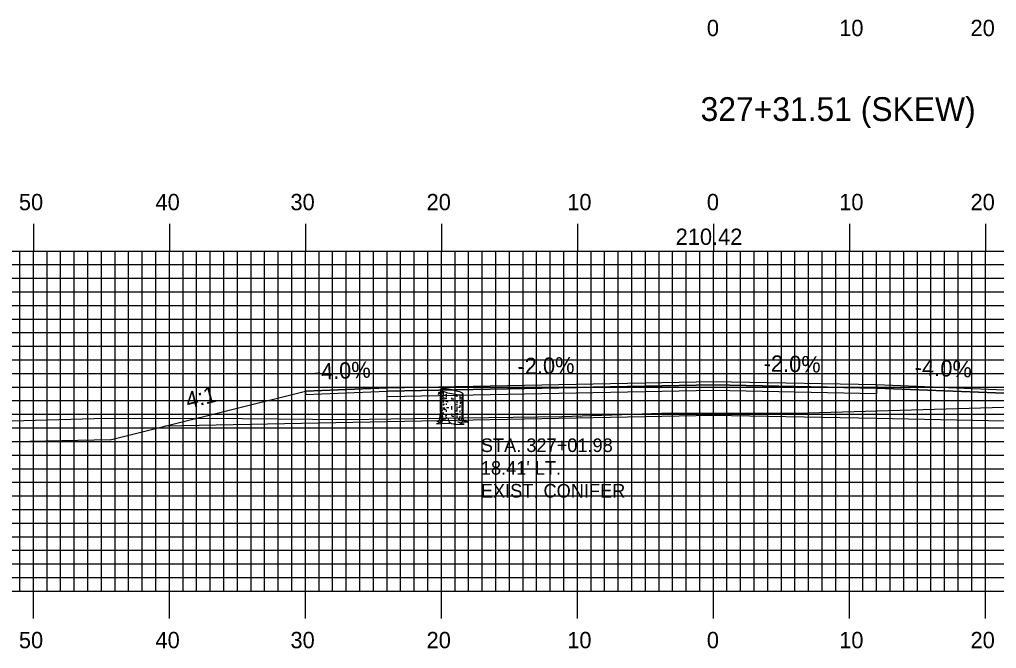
# Model space of a CAD drawing. Extents: x 1821605 to 1821948, y 442591 to 442811.
# Drawn here: x 1821719.7 to 1821791.6, y 442644.4 to 442690.7 of the extents above; entities that cross this region are included whole.
import ezdxf

# ---------------------------------------------------------------- set-up
doc = ezdxf.new("R2010")
doc.units = 0
for name, color, linetype in [('ANNOTATION', 7, 'Continuous'), ('D_Roadway_Centerline', 7, 'Continuous'), ('D_Roadway_Centerline_Text', 7, 'Continuous'), ('D_Roadway_Edge_Shoulder', 7, 'Continuous'), ('D_Roadway_Edge_TW', 7, 'Continuous'), ('D_Roadway_Pavement', 7, 'Continuous'), ('D_Roadway_SubGrade', 7, 'Continuous'), ('D_Text_Monospaced', 7, 'Continuous'), ('H_V ANNOTATION', 7, 'Continuous'), ('M_Trees_Conifer_Pay', 7, 'Continuous'), ('MAJOR', 7, 'Continuous'), ('MINOR', 7, 'Continuous'), ('S_Roadway_Centerline', 7, 'Continuous')]:
    doc.layers.add(name, color=color, linetype=linetype)

msp = doc.modelspace()

# ---------------------------------------------------------------- linework, layer by layer
at = {"layer": 'ANNOTATION'}
msp.add_line((1821726.395, 442659.778), (1821630.743, 442657.865), dxfattribs=at)
at = {"layer": 'D_Roadway_Centerline'}
msp.add_lwpolyline([(1821726.395, 442659.778), (1821730.395, 442660.778), (1821740.743, 442663.365), (1821746.743, 442663.605), (1821770.743, 442664.085), (1821782.743, 442663.845), (1821792.743, 442663.445), (1821802.743, 442660.945), (1821806.743, 442659.945), (1821816.975, 442662.503), (1821818.225, 442662.782), (1821819.475, 442662.992), (1821820.725, 442663.135), (1821821.975, 442663.209)], dxfattribs=at)
at = {"layer": 'D_Roadway_Edge_Shoulder'}
for points in [[(1821746.743, 442663.605), (1821740.743, 442663.365), (1821740.743, 442663.115), (1821746.743, 442663.355)], [(1821782.743, 442663.845), (1821792.743, 442663.445), (1821792.743, 442663.195), (1821782.743, 442663.595)]]:
    msp.add_lwpolyline(points, close=True, dxfattribs=at)
at = {"layer": 'D_Roadway_Edge_TW'}
msp.add_lwpolyline([(1821746.743, 442663.355), (1821746.743, 442663.605), (1821770.743, 442664.085), (1821782.743, 442663.845), (1821782.743, 442663.595), (1821770.743, 442663.835)], close=True, dxfattribs=at)
at = {"layer": 'D_Roadway_Pavement'}
msp.add_lwpolyline([(1821746.743, 442662.939), (1821746.743, 442663.355), (1821770.743, 442663.835), (1821782.743, 442663.595), (1821782.743, 442663.179), (1821770.743, 442663.419)], close=True, dxfattribs=at)
at = {"layer": 'D_Roadway_SubGrade'}
msp.add_lwpolyline([(1821746.743, 442661.105), (1821730.395, 442660.778), (1821740.743, 442663.365), (1821740.743, 442663.115), (1821746.743, 442663.355), (1821770.743, 442663.835), (1821782.743, 442663.595), (1821792.743, 442663.195), (1821792.743, 442663.445), (1821802.743, 442660.945), (1821782.743, 442661.345), (1821770.743, 442661.585)], close=True, dxfattribs=at)
at = {"layer": 'M_Trees_Conifer_Pay'}
for p, q in [((1821750.674, 442661.839), (1821750.674, 442663.486)), ((1821750.745, 442663.414), (1821750.745, 442663.251)), ((1821750.863, 442663.353), (1821750.863, 442663.13)), ((1821750.745, 442663.183), (1821750.745, 442663.056)), ((1821750.745, 442662.869), (1821750.745, 442662.533)), ((1821750.806, 442662.858), (1821750.857, 442662.798)), ((1821750.863, 442663.041), (1821750.863, 442662.994)), ((1821750.863, 442662.659), (1821750.863, 442662.527)), ((1821751.091, 442663.157), (1821751.091, 442662.957)), ((1821751.091, 442662.899), (1821751.091, 442662.811)), ((1821751.482, 442662.883), (1821751.482, 442662.788)), ((1821751.887, 442663.115), (1821751.887, 442662.947)), ((1821751.887, 442662.71), (1821751.887, 442662.473)), ((1821752.107, 442663.094), (1821752.107, 442662.862)), ((1821752.107, 442662.821), (1821752.107, 442662.747)), ((1821752.232, 442663.102), (1821752.232, 442663.004)), ((1821752.232, 442662.93), (1821752.232, 442662.726)), ((1821752.232, 442662.668), (1821752.232, 442662.469)), ((1821752.291, 442663.113), (1821752.291, 442662.642)), ((1821752.291, 442662.578), (1821752.291, 442662.269)), ((1821752.338, 442661.429), (1821752.338, 442663.151)), ((1821750.745, 442662.496), (1821750.745, 442662.333)), ((1821750.745, 442662.286), (1821750.745, 442662.069)), ((1821750.745, 442662.038), (1821750.745, 442661.964)), ((1821750.745, 442661.924), (1821750.745, 442661.75)), ((1821750.863, 442662.416), (1821750.863, 442662.306)), ((1821750.863, 442662.17), (1821750.863, 442662.029)), ((1821751.091, 442662.463), (1821751.091, 442662.358)), ((1821751.091, 442661.991), (1821751.091, 442661.845)), ((1821751.482, 442662.269), (1821751.482, 442662.195)), ((1821751.482, 442662.17), (1821751.482, 442662.022)), ((1821751.887, 442662.228), (1821751.887, 442662.076)), ((1821751.887, 442662.033), (1821751.887, 442661.859)), ((1821752.107, 442662.344), (1821752.107, 442662.205)), ((1821752.107, 442661.933), (1821752.107, 442661.792)), ((1821752.232, 442662.422), (1821752.232, 442662.086)), ((1821752.232, 442662.033), (1821752.232, 442661.897)), ((1821752.291, 442662.222), (1821752.291, 442661.73)), ((1821750.863, 442661.802), (1821750.863, 442661.629)), ((1821751.091, 442661.613), (1821751.091, 442661.524)), ((1821751.482, 442661.73), (1821751.482, 442661.577)), ((1821751.887, 442661.582), (1821751.887, 442661.429)), ((1821752.107, 442661.53), (1821752.107, 442661.435)), ((1821752.232, 442661.798), (1821752.232, 442661.419)), ((1821752.291, 442661.676), (1821752.291, 442661.429)), ((1821751.67, 442660.972), (1821751.796, 442661.036)), ((1821752.107, 442661.036), (1821751.944, 442661.099))]:
    msp.add_line(p, q, dxfattribs=at)
for points in [[(1821750.857, 442662.984), (1821750.82, 442662.91), (1821750.773, 442662.967), (1821750.715, 442663.035), (1821750.623, 442663.229), (1821750.558, 442663.276), (1821750.527, 442663.283)], [(1821750.628, 442663.217), (1821750.552, 442663.225), (1821750.48, 442663.126)], [(1821750.842, 442662.731), (1821750.806, 442662.858), (1821750.742, 442662.973), (1821750.711, 442663.041), (1821750.642, 442663.187)], [(1821750.89, 442662.947), (1821750.921, 442662.862), (1821750.925, 442662.794), (1821750.894, 442662.731)], [(1821751.02, 442662.057), (1821751.007, 442661.981), (1821750.96, 442661.991), (1821750.972, 442662.158)], [(1821752.159, 442662.456), (1821752.165, 442662.552), (1821752.121, 442662.529), (1821752.121, 442662.434)], [(1821750.674, 442661.839), (1821750.623, 442661.577), (1821750.606, 442661.304), (1821750.548, 442661.178), (1821750.413, 442661.147), (1821750.643, 442661.11), (1821750.643, 442661.11), (1821750.637, 442661.063), (1821750.39, 442660.968), (1821750.664, 442660.985), (1821751.02, 442661.005), (1821751.341, 442660.995), (1821751.335, 442661.077), (1821751.483, 442660.995), (1821751.67, 442660.972), (1821751.646, 442660.904), (1821751.913, 442660.947), (1821752.134, 442660.92), (1821752.426, 442660.937), (1821752.138, 442660.995), (1821752.107, 442661.036), (1821752.27, 442661.094), (1821752.506, 442661.104), (1821752.747, 442661.104), (1821752.405, 442661.162), (1821752.364, 442661.242), (1821752.338, 442661.429)], [(1821750.847, 442661.551), (1821750.773, 442661.446), (1821750.768, 442661.273), (1821750.643, 442661.11)], [(1821750.748, 442661.697), (1821750.742, 442661.551), (1821750.695, 442661.483), (1821750.684, 442661.283)], [(1821750.806, 442661.057), (1821750.82, 442661.195), (1821750.894, 442661.324)], [(1821751.084, 442661.446), (1821751.073, 442661.32), (1821750.999, 442661.277)], [(1821751.335, 442661.077), (1821751.26, 442661.219), (1821751.251, 442661.32)], [(1821751.823, 442661.147), (1821751.755, 442661.242), (1821751.728, 442661.382)], [(1821752.049, 442661.388), (1821752.049, 442661.256), (1821752.138, 442661.157)], [(1821752.212, 442661.361), (1821752.206, 442661.246), (1821752.259, 442661.157), (1821752.27, 442661.094)], [(1821752.29, 442661.382), (1821752.311, 442661.304), (1821752.331, 442661.209)]]:
    msp.add_lwpolyline(points, dxfattribs=at)
for centre, radius, start, end in [((1821750.696, 442663.486), 0.0226, 156.59265, 168.2806), ((1821750.696, 442663.486), 0.0226, 168.2806, 179.96855), ((1821750.7, 442663.486), 0.0264, 179.96855, 190.7806), ((1821750.705, 442663.487), 0.0314, 190.7806, 203.48418), ((1821750.707, 442663.36), 0.0334, 185.78494, 196.05154), ((1821750.717, 442663.363), 0.0441, 196.05154, 210), ((1821750.7, 442663.485), 0.0264, 145.7806, 156.59265), ((1821750.725, 442663.496), 0.0527, 203.48418, 213.2806), ((1821750.704, 442663.482), 0.0314, 133.07702, 145.7806), ((1821750.733, 442663.372), 0.0624, 210, 228.74941), ((1821750.749, 442663.511), 0.0817, 213.2806, 227.61132), ((1821750.719, 442663.466), 0.0527, 123.2806, 133.07702), ((1821750.734, 442663.442), 0.0817, 108.94987, 123.2806), ((1821750.806, 442663.454), 0.172, 228.74941, 240), ((1821750.863, 442663.636), 0.251, 227.61132, 235.7806), ((1821750.789, 442663.282), 0.251, 100.7806, 108.94987), ((1821751.173, 442664.092), 0.802, 235.7806, 251.94061), ((1821750.892, 442662.741), 0.802, 84.62059, 100.7806), ((1821752.529, 442668.253), 5.179, 251.94061, 258.2806), ((1821750.482, 442658.383), 5.179, 78.2806, 84.62059), ((1821750.482, 442658.383), 5.179, 71.94061, 78.2806), ((1821751.839, 442662.545), 0.802, 55.7806, 71.94061), ((1821750.707, 442663.205), 0.0334, 185.78494, 196.05154), ((1821750.707, 442662.761), 0.0334, 185.78494, 196.05154), ((1821750.717, 442663.208), 0.0441, 196.05154, 210), ((1821750.733, 442663.217), 0.0624, 210, 228.74941), ((1821750.806, 442663.3), 0.172, 228.74941, 240), ((1821751.005, 442663.645), 0.571, 240, 242.9763), ((1821751.005, 442663.201), 0.571, 242.95715, 255.55072), ((1821751.005, 442663.799), 0.571, 247.58675, 255.56834), ((1821751.005, 442663.645), 0.571, 255.63335, 261.8968), ((1821751.506, 442667.163), 4.124, 261.8968, 263.76196), ((1821751.507, 442666.93), 4.124, 262.94416, 264.21507), ((1821751.506, 442666.719), 4.124, 264.04957, 266.29476), ((1821752.529, 442668.253), 5.179, 258.2806, 264.62059), ((1821751.507, 442666.93), 4.124, 269.64186, 270), ((1821751.507, 442666.93), 4.124, 270, 271.92488), ((1821751.506, 442667.163), 4.124, 273.26691, 275.3045), ((1821752.119, 442663.895), 0.802, 264.62059, 280.7806), ((1821752.008, 442663.412), 0.571, 282.01543, 293.14027), ((1821752.007, 442663.201), 0.571, 292.94134, 300), ((1821752.222, 442663.354), 0.251, 280.7806, 288.94988), ((1821752.149, 442663), 0.251, 47.61132, 55.7806), ((1821752.008, 442663.412), 0.571, 299.66328, 300), ((1821752.207, 442663.067), 0.172, 300, 311.25059), ((1821752.277, 442663.194), 0.0817, 288.94988, 303.2806), ((1821752.263, 442663.125), 0.0817, 33.2806, 47.61132), ((1821752.28, 442662.985), 0.0624, 311.25059, 330), ((1821752.293, 442663.17), 0.0527, 303.2806, 313.07702), ((1821752.307, 442663.155), 0.0314, 313.07702, 325.7806), ((1821752.287, 442663.141), 0.0527, 23.48418, 33.2806), ((1821752.312, 442663.152), 0.0264, 325.7806, 336.59265), ((1821752.295, 442662.975), 0.0441, 330, 343.94846), ((1821752.306, 442663.149), 0.0314, 10.7806, 23.48418), ((1821752.315, 442663.15), 0.0226, 336.59265, 348.2806), ((1821752.311, 442663.15), 0.0264, 359.96855, 10.7806), ((1821752.315, 442663.15), 0.0226, 348.2806, 359.96855), ((1821752.306, 442662.972), 0.0334, 0, 16.05154), ((1821752.306, 442662.972), 0.0334, 343.94846, 360), ((1821750.708, 442662.526), 0.0334, 185.78494, 196.05154), ((1821750.708, 442662.316), 0.0334, 185.78494, 196.05154), ((1821750.708, 442661.881), 0.0334, 185.78494, 196.05154), ((1821750.719, 442662.529), 0.0441, 196.05154, 210), ((1821750.719, 442662.319), 0.0441, 196.05154, 210), ((1821750.719, 442661.884), 0.0441, 196.05154, 210), ((1821750.735, 442662.538), 0.0624, 210, 228.74941), ((1821750.735, 442662.328), 0.0624, 210, 228.74941), ((1821750.735, 442661.893), 0.0624, 210, 228.74941), ((1821750.807, 442662.62), 0.172, 228.74941, 240), ((1821750.807, 442662.41), 0.172, 228.74941, 240), ((1821750.807, 442661.976), 0.172, 228.74941, 240), ((1821751.006, 442662.965), 0.571, 240, 242.81041), ((1821751.006, 442662.755), 0.571, 240, 242.81041), ((1821751.006, 442662.519), 0.571, 242.81041, 254.60173), ((1821751.006, 442662.965), 0.571, 253.07038, 261.8968), ((1821751.507, 442666.483), 4.124, 261.8968, 262.38753), ((1821751.507, 442666.273), 4.124, 264.54309, 266.85066), ((1821751.507, 442666.273), 4.124, 269.64186, 270), ((1821751.507, 442666.483), 4.124, 273.33241, 275.91902), ((1821751.507, 442666.036), 4.124, 273.68066, 275.28397), ((1821751.507, 442666.273), 4.124, 276.85262, 278.1032), ((1821752.008, 442662.755), 0.571, 278.1032, 280.72928), ((1821752.008, 442662.755), 0.571, 293.14027, 300), ((1821752.008, 442662.519), 0.571, 293.14027, 300), ((1821752.008, 442662.965), 0.571, 299.66328, 300), ((1821752.207, 442662.62), 0.172, 300, 311.25059), ((1821752.207, 442662.41), 0.172, 300, 311.25059), ((1821752.207, 442662.174), 0.172, 300, 311.25059), ((1821752.28, 442662.538), 0.0624, 311.25059, 330), ((1821752.28, 442662.328), 0.0624, 311.25059, 330), ((1821752.28, 442662.091), 0.0624, 311.25059, 330), ((1821752.295, 442662.529), 0.0441, 330, 343.94846), ((1821752.295, 442662.319), 0.0441, 330, 343.94846), ((1821752.295, 442662.082), 0.0441, 330, 343.94846), ((1821752.306, 442662.526), 0.0334, 0, 16.05154), ((1821752.306, 442662.526), 0.0334, 343.94846, 360), ((1821752.306, 442662.316), 0.0334, 0, 16.05154), ((1821752.306, 442662.316), 0.0334, 343.94846, 360), ((1821752.306, 442662.079), 0.0334, 0, 16.05154), ((1821752.306, 442662.079), 0.0334, 343.94846, 360), ((1821752.306, 442661.881), 0.0334, 0, 16.05154), ((1821750.708, 442661.465), 0.0334, 185.78494, 196.05154), ((1821750.719, 442661.468), 0.0441, 196.05154, 210), ((1821750.735, 442661.477), 0.0624, 210, 228.74941), ((1821750.807, 442661.56), 0.172, 228.74941, 240), ((1821751.006, 442662.321), 0.571, 240, 250.70928), ((1821751.006, 442662.125), 0.571, 242.72792, 251.49327), ((1821751.006, 442661.905), 0.571, 258.36297, 261.8968), ((1821751.507, 442665.423), 4.124, 261.8968, 262.63158), ((1821751.507, 442665.643), 4.124, 263.21039, 264.21507), ((1821751.507, 442665.643), 4.124, 269.86721, 270), ((1821751.507, 442665.643), 4.124, 270, 272.18834), ((1821751.507, 442665.838), 4.124, 274.16025, 276.50094), ((1821751.507, 442665.423), 4.124, 276.48798, 277.55621), ((1821752.019, 442662.327), 0.571, 291.97323, 298.76314), ((1821752.008, 442662.125), 0.571, 293.14027, 300), ((1821752.008, 442661.905), 0.571, 295.46862, 300), ((1821752.207, 442661.78), 0.172, 300, 311.25059), ((1821752.207, 442661.56), 0.172, 300, 311.25059), ((1821752.28, 442661.698), 0.0624, 311.25059, 330), ((1821752.28, 442661.477), 0.0624, 311.25059, 330), ((1821752.295, 442661.689), 0.0441, 330, 343.94846), ((1821752.295, 442661.468), 0.0441, 330, 343.94846), ((1821752.306, 442661.686), 0.0334, 0, 16.05154), ((1821752.306, 442661.686), 0.0334, 343.94846, 360), ((1821752.306, 442661.465), 0.0334, 0, 16.05154), ((1821752.306, 442661.465), 0.0334, 343.94846, 360)]:
    msp.add_arc(centre, radius, start, end, dxfattribs=at)
at = {"layer": 'MAJOR'}
for p, q in [((1821720.743, 442675.669), (1821720.743, 442673.665)), ((1821730.743, 442675.669), (1821730.743, 442673.665)), ((1821740.743, 442675.669), (1821740.743, 442673.665)), ((1821750.743, 442675.669), (1821750.743, 442673.665)), ((1821760.743, 442675.669), (1821760.743, 442673.665)), ((1821770.743, 442675.669), (1821770.743, 442673.665)), ((1821780.743, 442675.669), (1821780.743, 442673.665)), ((1821790.743, 442675.669), (1821790.743, 442673.665)), ((1821630.743, 442673.665), (1821910.743, 442673.665)), ((1821630.743, 442673.665), (1821910.743, 442673.665)), ((1821720.743, 442648.665), (1821720.743, 442673.665)), ((1821730.743, 442648.665), (1821730.743, 442673.665)), ((1821740.743, 442648.665), (1821740.743, 442673.665)), ((1821750.743, 442648.665), (1821750.743, 442673.665)), ((1821760.743, 442648.665), (1821760.743, 442673.665)), ((1821770.743, 442648.665), (1821770.743, 442673.665)), ((1821780.743, 442648.665), (1821780.743, 442673.665)), ((1821790.743, 442648.665), (1821790.743, 442673.665)), ((1821630.743, 442668.665), (1821910.743, 442668.665)), ((1821630.743, 442663.665), (1821910.743, 442663.665)), ((1821630.743, 442658.665), (1821910.743, 442658.665)), ((1821630.743, 442653.665), (1821910.743, 442653.665)), ((1821630.743, 442648.665), (1821910.743, 442648.665)), ((1821630.743, 442648.665), (1821910.743, 442648.665)), ((1821720.743, 442646.661), (1821720.743, 442648.665)), ((1821730.743, 442646.661), (1821730.743, 442648.665)), ((1821740.743, 442646.661), (1821740.743, 442648.665)), ((1821750.743, 442646.661), (1821750.743, 442648.665)), ((1821760.743, 442646.661), (1821760.743, 442648.665)), ((1821770.743, 442646.661), (1821770.743, 442648.665)), ((1821780.743, 442646.661), (1821780.743, 442648.665)), ((1821790.743, 442646.661), (1821790.743, 442648.665))]:
    msp.add_line(p, q, dxfattribs=at)
at = {"layer": 'MINOR'}
for p, q in [((1821719.743, 442648.665), (1821719.743, 442673.665)), ((1821721.743, 442648.665), (1821721.743, 442673.665)), ((1821722.743, 442648.665), (1821722.743, 442673.665)), ((1821723.743, 442648.665), (1821723.743, 442673.665)), ((1821724.743, 442648.665), (1821724.743, 442673.665)), ((1821725.743, 442648.665), (1821725.743, 442673.665)), ((1821726.743, 442648.665), (1821726.743, 442673.665)), ((1821727.743, 442648.665), (1821727.743, 442673.665)), ((1821728.743, 442648.665), (1821728.743, 442673.665)), ((1821729.743, 442648.665), (1821729.743, 442673.665)), ((1821731.743, 442648.665), (1821731.743, 442673.665)), ((1821732.743, 442648.665), (1821732.743, 442673.665)), ((1821733.743, 442648.665), (1821733.743, 442673.665)), ((1821734.743, 442648.665), (1821734.743, 442673.665)), ((1821735.743, 442648.665), (1821735.743, 442673.665)), ((1821736.743, 442648.665), (1821736.743, 442673.665)), ((1821737.743, 442648.665), (1821737.743, 442673.665)), ((1821738.743, 442648.665), (1821738.743, 442673.665)), ((1821739.743, 442648.665), (1821739.743, 442673.665)), ((1821741.743, 442648.665), (1821741.743, 442673.665)), ((1821742.743, 442648.665), (1821742.743, 442673.665)), ((1821743.743, 442648.665), (1821743.743, 442673.665)), ((1821744.743, 442648.665), (1821744.743, 442673.665)), ((1821745.743, 442648.665), (1821745.743, 442673.665)), ((1821746.743, 442648.665), (1821746.743, 442673.665)), ((1821747.743, 442648.665), (1821747.743, 442673.665)), ((1821748.743, 442648.665), (1821748.743, 442673.665)), ((1821749.743, 442648.665), (1821749.743, 442673.665)), ((1821751.743, 442648.665), (1821751.743, 442673.665)), ((1821752.743, 442648.665), (1821752.743, 442673.665)), ((1821753.743, 442648.665), (1821753.743, 442673.665)), ((1821754.743, 442648.665), (1821754.743, 442673.665)), ((1821755.743, 442648.665), (1821755.743, 442673.665)), ((1821756.743, 442648.665), (1821756.743, 442673.665)), ((1821757.743, 442648.665), (1821757.743, 442673.665)), ((1821758.743, 442648.665), (1821758.743, 442673.665)), ((1821759.743, 442648.665), (1821759.743, 442673.665)), ((1821761.743, 442648.665), (1821761.743, 442673.665)), ((1821762.743, 442648.665), (1821762.743, 442673.665)), ((1821763.743, 442648.665), (1821763.743, 442673.665)), ((1821764.743, 442648.665), (1821764.743, 442673.665)), ((1821765.743, 442648.665), (1821765.743, 442673.665)), ((1821766.743, 442648.665), (1821766.743, 442673.665)), ((1821767.743, 442648.665), (1821767.743, 442673.665)), ((1821768.743, 442648.665), (1821768.743, 442673.665)), ((1821769.743, 442648.665), (1821769.743, 442673.665)), ((1821771.743, 442648.665), (1821771.743, 442673.665)), ((1821772.743, 442648.665), (1821772.743, 442673.665)), ((1821773.743, 442648.665), (1821773.743, 442673.665)), ((1821774.743, 442648.665), (1821774.743, 442673.665)), ((1821775.743, 442648.665), (1821775.743, 442673.665)), ((1821776.743, 442648.665), (1821776.743, 442673.665)), ((1821777.743, 442648.665), (1821777.743, 442673.665)), ((1821778.743, 442648.665), (1821778.743, 442673.665)), ((1821779.743, 442648.665), (1821779.743, 442673.665)), ((1821781.743, 442648.665), (1821781.743, 442673.665)), ((1821782.743, 442648.665), (1821782.743, 442673.665)), ((1821783.743, 442648.665), (1821783.743, 442673.665)), ((1821784.743, 442648.665), (1821784.743, 442673.665)), ((1821785.743, 442648.665), (1821785.743, 442673.665)), ((1821786.743, 442648.665), (1821786.743, 442673.665)), ((1821787.743, 442648.665), (1821787.743, 442673.665)), ((1821788.743, 442648.665), (1821788.743, 442673.665)), ((1821789.743, 442648.665), (1821789.743, 442673.665)), ((1821630.743, 442672.665), (1821910.743, 442672.665)), ((1821630.743, 442671.665), (1821910.743, 442671.665)), ((1821630.743, 442670.665), (1821910.743, 442670.665)), ((1821630.743, 442669.665), (1821910.743, 442669.665)), ((1821630.743, 442667.665), (1821910.743, 442667.665)), ((1821630.743, 442666.665), (1821910.743, 442666.665)), ((1821630.743, 442665.665), (1821910.743, 442665.665)), ((1821630.743, 442664.665), (1821910.743, 442664.665)), ((1821630.743, 442662.665), (1821910.743, 442662.665)), ((1821630.743, 442661.665), (1821910.743, 442661.665)), ((1821630.743, 442660.665), (1821910.743, 442660.665)), ((1821630.743, 442659.665), (1821910.743, 442659.665)), ((1821630.743, 442657.665), (1821910.743, 442657.665)), ((1821630.743, 442656.665), (1821910.743, 442656.665)), ((1821630.743, 442655.665), (1821910.743, 442655.665)), ((1821630.743, 442654.665), (1821910.743, 442654.665)), ((1821630.743, 442652.665), (1821910.743, 442652.665)), ((1821630.743, 442651.665), (1821910.743, 442651.665)), ((1821630.743, 442650.665), (1821910.743, 442650.665)), ((1821630.743, 442649.665), (1821910.743, 442649.665))]:
    msp.add_line(p, q, dxfattribs=at)
at = {"layer": 'S_Roadway_Centerline'}
msp.add_lwpolyline([(1821714.848, 442661.053), (1821726.061, 442661.379), (1821736.107, 442661.342), (1821743.844, 442661.276), (1821747.03, 442661.334), (1821759.62, 442661.497), (1821767.67, 442661.773), (1821776.853, 442661.75), (1821792.926, 442662.215), (1821794.709, 442662.281), (1821795.333, 442662.294), (1821796.815, 442662.342), (1821809.192, 442662.796), (1821823.978, 442663.274), (1821827.054, 442663.481), (1821829.355, 442663.576), (1821838.043, 442663.824), (1821838.284, 442663.831), (1821838.429, 442663.84), (1821838.613, 442663.848), (1821845.708, 442664.076)], dxfattribs=at)

# ---------------------------------------------------------------- texts
at = {"layer": 'ANNOTATION'}
for s, rotation, p in [('-4.0%', 2.29061, (1821741.375, 442664.192)), ('-2.0%', 1.14576, (1821756.349, 442664.598)), ('-2.0%', 358.85424, (1821774.429, 442664.812)), ('-4.0%', 357.70939, (1821785.535, 442664.535)), ('4:1', 14.03624, (1821732.105, 442662.067))]:
    msp.add_text(s, height=1.2, rotation=rotation, dxfattribs=at).set_placement(p)
at = {"layer": 'D_Roadway_Centerline'}
for s, p in [('C', (1821770.738, 442664.085)), ('L', (1821770.743, 442664.078))]:
    msp.add_text(s, height=0.0146, dxfattribs=at).set_placement(p)
at = {"layer": 'D_Roadway_Centerline_Text'}
msp.add_text('210.42', height=1.2, dxfattribs=at).set_placement((1821767.966, 442674.115))
at = {"layer": 'D_Text_Monospaced'}
for s, height, p in [('STA. 327+01.98', 0.99996, (1821753.641, 442658.889)), ("18.41' LT.", 1, (1821753.641, 442657.221)), ('EXIST. CONIFER', 0.99996, (1821753.641, 442655.541))]:
    msp.add_text(s, height=height, dxfattribs=at).set_placement(p)
at = {"layer": 'H_V ANNOTATION'}
for s, height, p in [('0', 1.2, (1821770.261, 442689.465)), ('10', 1.2, (1821779.994, 442689.465)), ('20', 1.2, (1821789.651, 442689.465)), ('327+31.51 (SKEW)', 1.74996, (1821769.801, 442683.226)), ('50', 1.2, (1821719.672, 442676.665)), ('40', 1.2, (1821729.715, 442676.665)), ('30', 1.2, (1821739.641, 442676.665)), ('20', 1.2, (1821749.651, 442676.665)), ('10', 1.2, (1821759.994, 442676.665)), ('0', 1.2, (1821770.261, 442676.665)), ('10', 1.2, (1821779.994, 442676.665)), ('20', 1.2, (1821789.651, 442676.665)), ('50', 1.2, (1821719.672, 442644.465)), ('40', 1.2, (1821729.715, 442644.465)), ('30', 1.2, (1821739.641, 442644.465)), ('20', 1.2, (1821749.651, 442644.465)), ('10', 1.2, (1821759.994, 442644.465)), ('0', 1.2, (1821770.261, 442644.465)), ('10', 1.2, (1821779.994, 442644.465)), ('20', 1.2, (1821789.651, 442644.465))]:
    msp.add_text(s, height=height, dxfattribs=at).set_placement(p)

doc.saveas('drawing.dxf')
